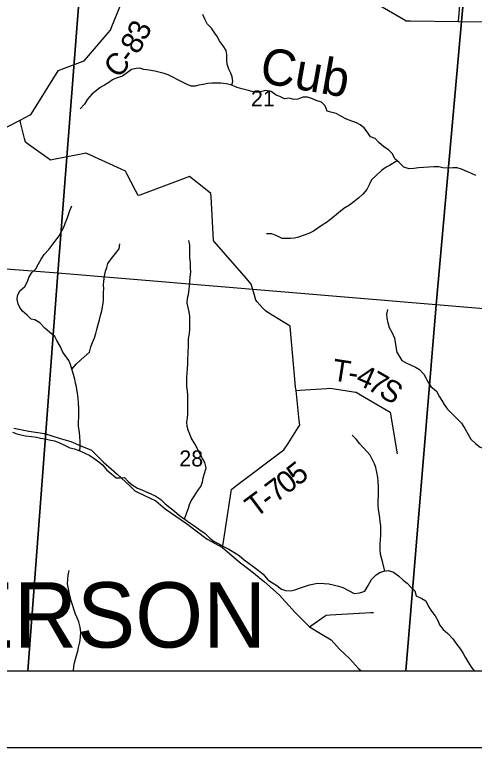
# Model space of a CAD drawing. Extents: x 0 to 42, y 0 to 22.
# Drawn here: x 2.801 to 3.401, y 14 to 14.957 of the extents above; entities that cross this region are included whole.
import ezdxf

# ---------------------------------------------------------------- set-up
doc = ezdxf.new("R2010")
doc.units = 0
for name, color, linetype in [('GM_X_County_Road', 7, 'Continuous'), ('GM_X_County_Road_Text', 7, 'Continuous'), ('GM_X_Minor_River', 7, 'Continuous'), ('GM_X_Minor_River_Text', 7, 'Continuous'), ('GM_X_Section', 7, 'Continuous'), ('GM_X_Section_Text', 7, 'Continuous'), ('GM_X_Township_Road', 7, 'Continuous'), ('GM_X_Township_Road_Text', 7, 'Continuous'), ('GM_X_Township_Text', 7, 'Continuous'), ('GM_X_Unincorporated', 7, 'Continuous'), ('SH_Cut_Line', 7, 'Continuous'), ('SH_Data', 7, 'Continuous')]:
    doc.layers.add(name, color=color, linetype=linetype)

msp = doc.modelspace()

# ---------------------------------------------------------------- linework, layer by layer
at = {"layer": 'GM_X_County_Road'}
for points in [[(3.24481, 14.98853), (3.30859, 14.95099), (3.31224, 14.94883), (3.31786, 14.94875), (3.37992, 14.94791), (3.44611, 14.947), (3.45008, 14.94693), (3.45596, 14.9469), (3.56941, 14.94637), (3.57221, 14.94635), (3.57927, 14.94612), (3.63844, 14.94416), (3.64113, 14.94407), (3.64598, 14.9388), (3.69274, 14.88797), (3.69321, 14.88746), (3.69812, 14.87971), (3.72039, 14.84793), (3.72784, 14.84091), (3.73728, 14.8385), (3.77408, 14.83911)], [(2.78193, 14.80561), (2.80818, 14.8193), (2.8213, 14.82614), (2.82277, 14.82691), (2.82709, 14.83389), (2.85566, 14.88002), (2.85817, 14.88408), (2.86294, 14.88584), (2.89072, 14.89607), (2.89169, 14.89643), (2.89745, 14.90312), (2.92318, 14.93305), (2.92615, 14.93651), (2.92812, 14.94143), (2.94277, 14.97809)], [(2.79997, 14.41702), (2.81947, 14.41284), (2.83992, 14.40979), (2.85923, 14.40389), (2.87438, 14.39933), (2.88763, 14.39401), (2.90126, 14.38831), (2.91677, 14.37293), (2.93493, 14.35699), (2.95158, 14.34161), (2.9582, 14.33496), (2.97051, 14.32908), (2.98565, 14.32186), (2.99776, 14.31141), (3.02539, 14.29224), (3.05226, 14.27192), (3.07236, 14.26082), (3.09427, 14.2423), (3.10865, 14.23147), (3.12738, 14.21628), (3.14649, 14.1992), (3.1673, 14.17604), (3.18599, 14.1574), (3.2006, 14.14889), (3.21441, 14.14034), (3.22539, 14.12838), (3.23844, 14.11604), (3.25017, 14.10294), (3.25342, 14.1)]]:
    msp.add_lwpolyline(points, dxfattribs=at)
at = {"layer": 'GM_X_Minor_River'}
for points in [[(3.08454, 14.86479), (3.08603, 14.8698), (3.0851, 14.87587), (3.08323, 14.88061), (3.08079, 14.88574), (3.07835, 14.89238), (3.078, 14.89788), (3.07802, 14.9047), (3.07709, 14.91001), (3.07314, 14.91609), (3.06825, 14.92313), (3.06581, 14.92806), (3.06243, 14.93281), (3.05791, 14.93928), (3.05244, 14.94498), (3.04963, 14.9503), (3.04663, 14.95713)], [(3.40316, 14.74671), (3.39674, 14.74977), (3.39126, 14.75226), (3.38446, 14.75532), (3.37879, 14.75704), (3.37293, 14.75707), (3.36669, 14.75633), (3.36026, 14.75692), (3.35496, 14.75827), (3.34853, 14.75811), (3.34172, 14.75756), (3.33472, 14.75721), (3.32848, 14.75667), (3.32242, 14.75593), (3.31618, 14.75539), (3.30938, 14.75788), (3.30297, 14.76397), (3.2975, 14.76873), (3.2945, 14.77499), (3.28903, 14.78051), (3.283, 14.78432), (3.27639, 14.78985), (3.27169, 14.79536), (3.26583, 14.79747), (3.26207, 14.80279), (3.25736, 14.80906), (3.25227, 14.81325), (3.24736, 14.81573), (3.24132, 14.81765), (3.23433, 14.82052), (3.22678, 14.82434), (3.22092, 14.82777), (3.21393, 14.82951), (3.20902, 14.83104), (3.20659, 14.83787), (3.20168, 14.84244), (3.19488, 14.84474), (3.18997, 14.84685), (3.18336, 14.84896), (3.17731, 14.84936), (3.17068, 14.84673), (3.16576, 14.84599), (3.15952, 14.84791), (3.15347, 14.8468), (3.14743, 14.85004), (3.14251, 14.85158), (3.1361, 14.85653), (3.12835, 14.85789), (3.12267, 14.8562), (3.11624, 14.85509), (3.11113, 14.85663), (3.10471, 14.85836), (3.09791, 14.86009), (3.09148, 14.86201), (3.08336, 14.86526), (3.07712, 14.8668), (3.07032, 14.8674), (3.06426, 14.86761), (3.0584, 14.86744), (3.05348, 14.86708), (3.04723, 14.86578), (3.04155, 14.86466), (3.03663, 14.86373), (3.03153, 14.86375), (3.02643, 14.86567), (3.01869, 14.86968), (3.01321, 14.87235), (3.0083, 14.87465), (3.00132, 14.87828), (2.99622, 14.88019), (2.99111, 14.88135), (2.98393, 14.88308), (2.97675, 14.88424), (2.96957, 14.88541), (2.96465, 14.88694), (2.95973, 14.88658), (2.95368, 14.88528), (2.94855, 14.88132), (2.94192, 14.87661), (2.93377, 14.87417), (2.92885, 14.87173), (2.9241, 14.86834), (2.91823, 14.86476), (2.91273, 14.86194), (2.90799, 14.85797), (2.90211, 14.85345), (2.89622, 14.84646), (2.89241, 14.84022), (2.88672, 14.83399)], [(3.30054, 14.76609), (3.29066, 14.75985), (3.28592, 14.75778), (3.28023, 14.75325), (3.27321, 14.74702), (3.26714, 14.74117), (3.26466, 14.73625), (3.26104, 14.7285), (3.25553, 14.72245), (3.25059, 14.71755), (3.24395, 14.71264), (3.23826, 14.70812), (3.23087, 14.70397), (3.22404, 14.69832), (3.21854, 14.6936), (3.21379, 14.68964), (3.20829, 14.68568), (3.20242, 14.6821), (3.19673, 14.67795), (3.19142, 14.67418), (3.18516, 14.67117), (3.17759, 14.66836), (3.17172, 14.6663), (3.16641, 14.66518), (3.16112, 14.66463), (3.15582, 14.66446), (3.15052, 14.66467), (3.14335, 14.66792), (3.13674, 14.6706), (3.12993, 14.67063)], [(2.86417, 14.51604), (2.8606, 14.52402), (2.85609, 14.53124), (2.85365, 14.53655), (2.84648, 14.54227), (2.84045, 14.5476), (2.83404, 14.55444), (2.82763, 14.55826), (2.82252, 14.55904), (2.81762, 14.56455), (2.8114, 14.5695), (2.80783, 14.57464), (2.80557, 14.57938), (2.80446, 14.58488), (2.80485, 14.58962), (2.80791, 14.59624), (2.81436, 14.60171), (2.81798, 14.60833), (2.8197, 14.61363), (2.82369, 14.62006), (2.82863, 14.62497), (2.83244, 14.63159), (2.83568, 14.63745), (2.83967, 14.64369), (2.84575, 14.65011), (2.85088, 14.65729), (2.85544, 14.66296), (2.85924, 14.66825), (2.86267, 14.6745), (2.86553, 14.6796), (2.86763, 14.68528), (2.86954, 14.69077), (2.87164, 14.69607), (2.87317, 14.70099), (2.87565, 14.70723)], [(3.02779, 14.5157), (3.02801, 14.52546), (3.02804, 14.53342), (3.02939, 14.54062), (3.02998, 14.5463), (3.02981, 14.55161), (3.02964, 14.55824), (3.02966, 14.56298), (3.02874, 14.56886), (3.02762, 14.57436), (3.02613, 14.58024), (3.02672, 14.58649), (3.02806, 14.59142), (3.02903, 14.59805), (3.02924, 14.60278), (3.02983, 14.60828), (3.03041, 14.61415), (3.03101, 14.62059), (3.03065, 14.62628), (3.03048, 14.63272), (3.02975, 14.63936), (3.02996, 14.6441), (3.02998, 14.64997), (3.02981, 14.65604), (3.0287, 14.66211)], [(2.89878, 14.51597), (2.90051, 14.52292), (2.9028, 14.52859), (2.90528, 14.53503), (2.90701, 14.54071), (2.90854, 14.54582), (2.91008, 14.55226), (2.9118, 14.55851), (2.91334, 14.56399), (2.91506, 14.57024), (2.91641, 14.57763), (2.917, 14.58369), (2.91721, 14.58957), (2.91723, 14.59431), (2.91744, 14.59904), (2.91726, 14.60378), (2.91766, 14.6089), (2.91825, 14.61553), (2.9196, 14.62197), (2.92132, 14.62689), (2.92285, 14.63181), (2.92742, 14.63862), (2.93293, 14.64485), (2.93768, 14.65127), (2.93865, 14.65753)], [(3.30054, 14.51512), (3.29905, 14.52347), (3.29813, 14.52916), (3.29739, 14.5339), (3.2942, 14.54112), (3.29063, 14.54795), (3.28858, 14.55459), (3.28728, 14.56066), (3.2871, 14.56559), (3.28807, 14.57165)], [(2.88627, 14.38704), (2.8868, 14.3932), (2.88682, 14.39889), (2.88628, 14.40609), (2.88591, 14.4114), (2.88461, 14.41937), (2.88463, 14.42525), (2.88503, 14.43132), (2.88486, 14.437), (2.88487, 14.44269), (2.88433, 14.45009), (2.88416, 14.45521), (2.88379, 14.45995), (2.88286, 14.46488), (2.88174, 14.47076), (2.88043, 14.47551), (2.87969, 14.48082), (2.87801, 14.48708), (2.87595, 14.49373), (2.87389, 14.50018), (2.87201, 14.50511), (2.86417, 14.51604)], [(2.87595, 14.49373), (2.88127, 14.50035), (2.88772, 14.50601), (2.89878, 14.51597)], [(3.02293, 14.29822), (3.02583, 14.30689), (3.02793, 14.31238), (3.02946, 14.31711), (3.03137, 14.32204), (3.03593, 14.32866), (3.0403, 14.33528), (3.04429, 14.34077), (3.04639, 14.34626), (3.04717, 14.35195), (3.04927, 14.35877), (3.05099, 14.36521), (3.0495, 14.37185), (3.0463, 14.37736), (3.04216, 14.38515), (3.03971, 14.39008), (3.03614, 14.39654), (3.03162, 14.40433), (3.02974, 14.40908), (3.02768, 14.4142), (3.02637, 14.41913), (3.02601, 14.42501), (3.02659, 14.43032), (3.02736, 14.43525), (3.02719, 14.44056), (3.0274, 14.44625), (3.02704, 14.45383), (3.02706, 14.46047), (3.0267, 14.4654), (3.02596, 14.47128), (3.02579, 14.47773), (3.02581, 14.4836), (3.0262, 14.48853), (3.0266, 14.4946), (3.027, 14.50029), (3.0272, 14.50503), (3.02779, 14.5157)], [(3.30054, 14.51512), (3.30655, 14.50532), (3.31316, 14.50189), (3.31807, 14.49941), (3.32431, 14.49655), (3.32941, 14.49331), (3.33507, 14.48742), (3.33789, 14.48267), (3.34072, 14.47735), (3.34429, 14.47146), (3.35203, 14.46499), (3.3558, 14.45796), (3.35862, 14.45303), (3.36163, 14.44771), (3.36635, 14.44163), (3.37257, 14.43535), (3.37899, 14.42926), (3.38427, 14.42356), (3.3886, 14.41634), (3.39274, 14.4095), (3.39669, 14.40266), (3.40273, 14.39696), (3.40878, 14.3922), (3.41913, 14.38836)], [(2.79848, 14.41148), (2.80396, 14.40956), (2.80925, 14.40822), (2.8155, 14.40707), (2.82306, 14.40609), (2.82987, 14.40532), (2.83498, 14.40397), (2.84084, 14.40282), (2.84614, 14.40166), (2.85314, 14.40012), (2.85862, 14.39821), (2.86542, 14.39516), (2.87317, 14.39134), (2.87922, 14.38981), (2.88603, 14.38713), (2.89208, 14.38484), (2.89926, 14.38121), (2.90492, 14.37741), (2.91115, 14.37284), (2.91625, 14.36846), (2.92134, 14.36219), (2.92776, 14.35705), (2.9338, 14.35191), (2.93891, 14.3519), (2.9444, 14.35245), (2.94912, 14.34712), (2.9544, 14.34294), (2.96139, 14.33855), (2.96706, 14.33626), (2.97273, 14.33378), (2.97802, 14.33168), (2.98539, 14.32805), (2.99182, 14.32367), (2.99766, 14.31797), (3.00371, 14.31321), (3.00975, 14.30826), (3.01654, 14.30274), (3.02353, 14.29779), (3.02976, 14.29341), (3.03505, 14.28979), (3.04166, 14.28484), (3.04978, 14.27932), (3.05601, 14.27323), (3.06167, 14.26904), (3.06847, 14.26523), (3.07376, 14.26237), (3.08076, 14.25894), (3.08718, 14.25513), (3.09417, 14.25037), (3.10096, 14.24503), (3.10719, 14.24028), (3.1121, 14.23647), (3.11909, 14.23152), (3.1257, 14.226), (3.13154, 14.21859), (3.13759, 14.21497), (3.14325, 14.21135), (3.14967, 14.20678), (3.15459, 14.20506), (3.16178, 14.20428), (3.16689, 14.20578), (3.17314, 14.20803)], [(3.28432, 14.23011), (3.28169, 14.24089), (3.28057, 14.24563), (3.27889, 14.25227), (3.27834, 14.25834), (3.27836, 14.26555), (3.27857, 14.27162), (3.27896, 14.27654), (3.27917, 14.28356), (3.279, 14.28963), (3.27845, 14.29456), (3.2779, 14.29987), (3.27697, 14.30556), (3.27623, 14.31106), (3.27568, 14.31618), (3.27551, 14.32168), (3.27591, 14.32965), (3.2763, 14.33439), (3.27595, 14.34083), (3.27578, 14.34728), (3.27523, 14.35259), (3.27411, 14.35961), (3.27262, 14.36549), (3.27074, 14.37024), (3.26848, 14.37536), (3.2651, 14.38182), (3.26095, 14.38657), (3.25189, 14.39646), (3.2468, 14.40236), (3.24152, 14.40768)], [(2.87814, 14.1), (2.87834, 14.10539), (2.87911, 14.11032), (2.88045, 14.11506), (2.88198, 14.12017), (2.88351, 14.12548), (2.88428, 14.1304), (2.88601, 14.13741), (2.88717, 14.14386), (2.88756, 14.1503), (2.88683, 14.15713), (2.88477, 14.16377), (2.88289, 14.16909), (2.88064, 14.17402), (2.87876, 14.17915), (2.87688, 14.18465), (2.87482, 14.1913), (2.87351, 14.1968), (2.87239, 14.20211), (2.87127, 14.20704), (2.87016, 14.21368), (2.87037, 14.21956), (2.87095, 14.22468), (2.8723, 14.23093)], [(3.17314, 14.20803), (3.17807, 14.20953), (3.18584, 14.21217), (3.19057, 14.21329), (3.19587, 14.21422), (3.20496, 14.21382), (3.2112, 14.21361), (3.21707, 14.21226), (3.22387, 14.21035), (3.22955, 14.20881), (3.23673, 14.20481), (3.24428, 14.20099), (3.25167, 14.20192), (3.2583, 14.20398), (3.26248, 14.21118), (3.26705, 14.21932), (3.27294, 14.22518), (3.27806, 14.2282), (3.28317, 14.22989), (3.28904, 14.23101), (3.29547, 14.22871), (3.30227, 14.22395), (3.30812, 14.21825), (3.31341, 14.21463), (3.31793, 14.20968), (3.3234, 14.20436), (3.32547, 14.19809), (3.33246, 14.19447), (3.33775, 14.19142), (3.34132, 14.18401), (3.34528, 14.17775), (3.35018, 14.17166), (3.35394, 14.16483), (3.35582, 14.15989), (3.36072, 14.15381), (3.36676, 14.14867), (3.37299, 14.14183), (3.37826, 14.13423), (3.38297, 14.12833), (3.38674, 14.12263), (3.38919, 14.11789), (3.39333, 14.11105), (3.39766, 14.1044), (3.40115, 14.1)]]:
    msp.add_lwpolyline(points, dxfattribs=at)
at = {"layer": 'GM_X_Section'}
for points in [[(2.39051, 15.16957), (2.89713, 15.13046), (2.85743, 14.61911), (2.35157, 14.65861)], [(2.89713, 15.13046), (3.39711, 15.08946), (3.35135, 14.57775), (2.85743, 14.61911)], [(3.39711, 15.08946), (3.89198, 15.04961), (3.8526, 14.53574), (3.35135, 14.57775)]]:
    msp.add_lwpolyline(points, close=True, dxfattribs=at)
at = {"layer": 'GM_X_Township_Road'}
for points in [[(2.1, 16.7767), (2.1, 14.1), (4.80642, 14.1), (4.86241, 14.74155), (4.87577, 14.903), (4.88082, 14.9641), (4.90774, 15.22465), (4.90782, 15.22542), (4.91025, 15.24876), (4.91234, 15.26666), (4.91693, 15.30071), (4.92061, 15.33827), (4.92229, 15.35537), (4.9225, 15.35759), (4.92364, 15.36537), (4.92223, 15.37611), (4.92602, 15.41635), (4.9302, 15.46506), (4.93268, 15.49943), (4.95383, 15.74551), (4.96357, 15.8483), (4.97611, 15.98164)], [(3.39846, 15.16659), (3.39793, 15.15414), (3.39769, 15.1484), (3.38753, 15.03772), (3.37992, 14.94791)], [(3.07236, 14.26082), (3.07312, 14.26569), (3.08363, 14.33397), (3.08407, 14.33684), (3.08963, 14.34103), (3.15266, 14.38858), (3.15798, 14.39686), (3.17118, 14.4177), (3.17325, 14.42098), (3.17262, 14.42693), (3.16842, 14.46619), (3.16795, 14.47056), (3.16747, 14.476), (3.16098, 14.54973), (3.16094, 14.55014), (3.15286, 14.55505), (3.13177, 14.56784), (3.12838, 14.5699), (3.12446, 14.57431), (3.1179, 14.58168), (3.11588, 14.58396), (3.11403, 14.59053), (3.11003, 14.60478), (3.10362, 14.61227), (3.06178, 14.66088), (3.06078, 14.66203), (3.06031, 14.67037), (3.05758, 14.71963), (3.05737, 14.72319), (3.05243, 14.72711), (3.02926, 14.74553), (3.02004, 14.74217), (2.96463, 14.72133), (2.96251, 14.72053), (2.95899, 14.72728), (2.94757, 14.74915), (2.94584, 14.75245), (2.94025, 14.75499), (2.89536, 14.77545), (2.89415, 14.776), (2.88577, 14.77435), (2.85188, 14.7677), (2.84776, 14.76689), (2.84317, 14.77021), (2.81918, 14.78756), (2.81519, 14.79044), (2.81402, 14.79525), (2.80936, 14.81443), (2.80818, 14.8193)], [(3.16842, 14.46619), (3.17343, 14.46651), (3.20853, 14.46877), (3.21264, 14.46904), (3.2185, 14.46812), (3.24333, 14.46427), (3.24691, 14.46372), (3.25246, 14.46048), (3.29155, 14.43772), (3.2932, 14.42783), (3.29969, 14.38817), (3.30049, 14.38318)], [(3.18599, 14.1574), (3.18889, 14.15943), (3.20627, 14.17158), (3.2079, 14.17272), (3.21297, 14.173), (3.26591, 14.17595), (3.26944, 14.17614)]]:
    msp.add_lwpolyline(points, dxfattribs=at)
at = {"layer": 'GM_X_Unincorporated'}
for points in [[(2.7512, 14.1), (2.81839, 14.1), (2.85743, 14.61911), (2.35157, 14.65861), (2.30949, 14.13462)], [(2.81839, 14.1), (3.31162, 14.1), (3.35135, 14.57775), (2.85743, 14.61911)], [(3.31162, 14.1), (3.81143, 14.1), (3.8526, 14.53574), (3.35135, 14.57775)]]:
    msp.add_lwpolyline(points, close=True, dxfattribs=at)
at = {"layer": 'SH_Cut_Line'}
msp.add_lwpolyline([(2.1, 20.9), (2.1, 14.1), (8.05023, 14.1), (8.06868, 14.30702), (8.08338, 14.51358), (8.1512, 15.24132), (8.15761, 15.31908), (8.1628, 15.37905), (8.16837, 15.44612), (8.16945, 15.45935), (8.16983, 15.46634), (8.17227, 15.49063), (8.24231, 16.32059)], dxfattribs=at)
at = {"layer": 'SH_Data'}
for p, q in [((2.1, 14.1), (8.9, 14.1)), ((2, 14), (9, 14))]:
    msp.add_line(p, q, dxfattribs=at)

# ---------------------------------------------------------------- texts
at = {"layer": 'GM_X_County_Road_Text'}
for s, rotation, p in [('3', 65.26316, (2.97223, 14.92167)), ('8', 58.98192, (2.96162, 14.90367)), ('C', 49.56006, (2.93645, 14.87249)), ('-', 52.70068, (2.95265, 14.89157))]:
    msp.add_text(s, height=0.02841, rotation=rotation, dxfattribs=at).set_placement(p)
at = {"layer": 'GM_X_Minor_River_Text'}
msp.add_text('Cub', height=0.047349, rotation=349.99608, dxfattribs=at).set_placement((3.11934, 14.86868))
at = {"layer": 'GM_X_Section_Text'}
for s, p in [('21', (3.1096, 14.837)), ('28', (3.01606, 14.36685))]:
    msp.add_text(s, height=0.020928, rotation=0.00001, dxfattribs=at).set_placement(p)
at = {"layer": 'GM_X_Township_Road_Text'}
for s, rotation, p in [('T', 351.17854, (3.21427, 14.47958)), ('-', 351.16587, (3.23523, 14.47633)), ('4', 336.04975, (3.24476, 14.47511)), ('7', 329.95361, (3.25992, 14.46842)), ('S', 329.26017, (3.27487, 14.45978)), ('5', 38.37942, (3.17051, 14.34043)), ('0', 37.33622, (3.15615, 14.32947)), ('7', 36.98963, (3.14203, 14.31883)), ('T', 36.86647, (3.11564, 14.29904)), ('-', 36.89405, (3.13266, 14.3118))]:
    msp.add_text(s, height=0.02841, rotation=rotation, dxfattribs=at).set_placement(p)
at = {"layer": 'GM_X_Township_Text'}
msp.add_text('JEFFERSON', height=0.085227, rotation=0.00001, dxfattribs=at).set_placement((2.45192, 14.13038))

doc.saveas('drawing.dxf')
